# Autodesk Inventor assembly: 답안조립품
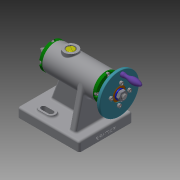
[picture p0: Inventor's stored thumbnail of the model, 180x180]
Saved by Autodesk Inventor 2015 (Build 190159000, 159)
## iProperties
Created: 2022-06
Part Number: 답안조립품
Document SubType Name: Assembly
Designer: 104589
Author: 104589
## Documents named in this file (18)
- C:\Users\104589\Desktop\720606V1006\답안조립품.iam
- C:\Users\104589\Desktop\720606V1006\나사.ipt
- C:\Users\104589\Desktop\720606V1006\나사축.ipt
- C:\Users\104589\Desktop\720606V1006\너트 M8.ipt
- C:\Users\104589\Desktop\720606V1006\돌림판.ipt
- C:\Users\104589\Desktop\720606V1006\멈춤나사 M3.ipt
- C:\Users\104589\Desktop\720606V1006\본체.ipt
- C:\Users\104589\Desktop\720606V1006\볼트 M3.ipt
- C:\Users\104589\Desktop\720606V1006\부시.ipt
- C:\Users\104589\Desktop\720606V1006\센터.ipt
- C:\Users\104589\Desktop\720606V1006\센터홀더.ipt
- C:\Users\104589\Desktop\720606V1006\슬리브.ipt
- C:\Users\104589\Desktop\720606V1006\와셔.ipt
- C:\Users\104589\Desktop\720606V1006\중공축.ipt
- C:\Users\104589\Desktop\720606V1006\커버.ipt
- C:\Users\104589\Desktop\720606V1006\키 4 x 4 x 10.ipt
- C:\Users\104589\Desktop\720606V1006\플랜지.ipt
- C:\Users\104589\Desktop\720606V1006\핸들.ipt
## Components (2 placed, 2 different names)
1. 플랜지:1 — 각도:2
2. 핸들:1
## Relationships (1: Angle 1)
- 각도:2 [Angle]: 플랜지:1
